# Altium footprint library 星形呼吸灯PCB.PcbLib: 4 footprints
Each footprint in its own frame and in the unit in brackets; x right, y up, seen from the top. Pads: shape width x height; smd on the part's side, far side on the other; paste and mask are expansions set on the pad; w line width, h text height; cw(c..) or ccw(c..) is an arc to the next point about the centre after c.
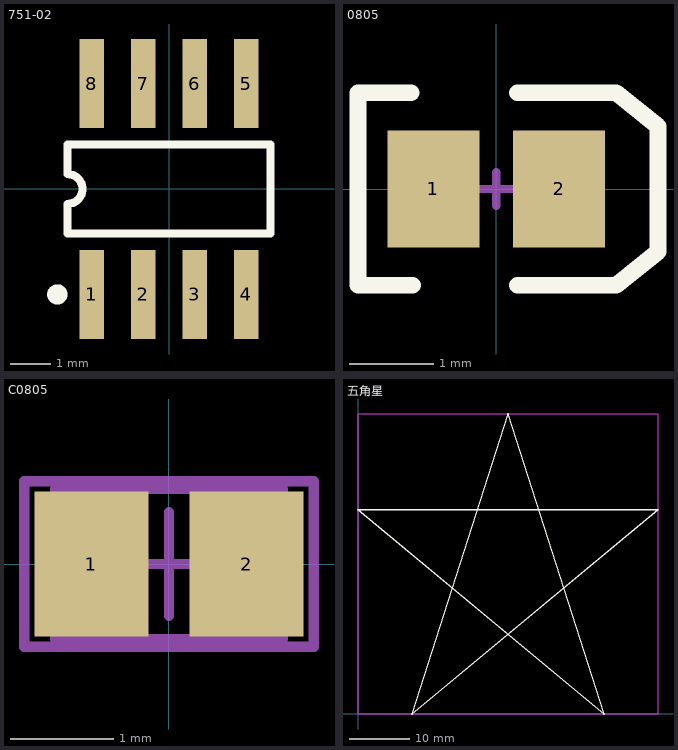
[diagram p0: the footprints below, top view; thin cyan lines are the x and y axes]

## 751-02 [mm] "Small Outline; 8 Leads; Body Width 3.9 mm; Pitch 1.27 mm"
height 1.75
pads (8):
  rect 0.6x2.2 smd: 1(-1.905,-2.6) 2(-0.635,-2.6) 3(0.635,-2.6) 4(1.905,-2.6) 5(1.905,2.6) 6(0.635,2.6) 7(-0.635,2.6) 8(-1.905,2.6)
Top Overlay:
  circle w0.25: c-2.755,-2.6 r0.125
  lines w0.2: -2.5,-1.1 2.5,-1.1 2.5,1.1 -2.5,1.1 -2.5,0.367 cw(c-2.5,0) -2.5,-0.367 -2.5,-1.1

## 0805 [mm] "SMT LED; 2 Flat Leads"
height 1.2
pads (2):
  rect 1.1x1.4 smd: 1(-0.75,0) 2(0.75,0)
Top Overlay:
  lines w0.2: -1.016,1.15 -1.651,1.15 -1.651,-1.15 -1,-1.15 ; 0.254,-1.15 1.397,-1.15 ; 0.254,1.15 1.397,1.15 ; 1.43,-1.15 1.93,-0.75 1.93,0.75 1.43,1.15
Mechanical 1:
  lines w0.1: -0.2,0 0.2,0 ; 0,-0.2 0,0.2

## C0805 [mm] "Chip Capacitor, Body 2.0x1.3mm, IPC High Density"
height 1.4
pads (2):
  rect 1.1x1.4 smd: 1(-0.75,0) 2(0.75,0)
Mechanical 13:
  lines w0.1: -1.1,-0.725 -1.1,0.725 1.1,0.725 1.1,-0.725 -1.1,-0.725
Mechanical 15:
  lines w0.1: -0.5,0 0.5,0 ; 0,-0.5 0,0.5 ; -1.4,-0.8 -1.4,0.8 1.4,0.8 1.4,-0.8 -1.4,-0.8
3D body: height 1.4, standoff 0, extent -1.1,-0.725 1.1,0.725

## 五角星 [mm] "Axial Device, Thru-Hole; 2 Leads; 0.4 in Pin Spacing"
height 2.032
Top Overlay:
  lines w0.254: 6.964,34.036 0,34.036 ; 43.036,34.036 49.911,34.036 50,34.036 ; 0,34.036 41,0 25,50 9,0 50,34.036 ; 0,34.036 50,34.036
Keep-Out Layer:
  lines w0.254: 0,0 50,0 50,50 0,50 0,0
